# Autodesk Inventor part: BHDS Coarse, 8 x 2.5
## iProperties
Shininess: 64.0
Length Units: 11272
Angle Units: 11279
Time Units: 11290
Mass Units: 11286
Length Display Precision: 3
Angle Display Precision: 2
Compacted: True
Part Number: BHDS Coarse, 8 x 2.5
Document SubType Name: Modeling
Created: 2003-05
Designer: Alan Rennick
Manufacturer: Standard
Standards Organization: Custom
Description: Bugle Head Drywall Screw, #8 Coarse Thd x 2.5
Density: 0.0
Volumn: 0.0
Area: 0.0
PropertySet Name: Model Information
Control State: 0
Master: False
Checked Out: False
Author: Alan Rennick
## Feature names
1. Revolution1
2. Extrusion1
3. Circular Pattern1
4. Fillet1
5. Thread1A
6. Thread1B
7. Thread1C
8. Thread2A
9. Thread2B
10. Thread2C
